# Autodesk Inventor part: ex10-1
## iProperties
Author: E. MOSS
Length Units: 11269
Angle Units: 11279
Time Units: 11290
Mass Units: 11283
Shininess: 3
Angle Display Precision: 2
Document Length Units: 11269
Document Angle Units: 11283
Document Time Units: 11279
Document Mass Units: 11290
Document Length Units Precision: 3
Document Angle Units Precision: 2
Compacted: False
PropertySet Name: _Private Model Information
Created: 2001-08
Part Number: ex10-1
Material: Aluminum-6061
Document SubType Name: Sheet Metal
Designer: E. MOSS
Control State: 0
Master: False
Checked Out: False
PropertySet Name: Design Tracking Control
Density: 0.0
Volumn: 0.0
Area: 0.0
PropertySet Name: Model Information
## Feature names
1. Hole1
2. Plate1
3. Plate2
4. Bend1
5. Plate3
6. Bend2
7. Plate4
8. Bend3
9. Plate5
10. Bend4
11. Plate6
12. Bend5
13. Plate7
14. Bend6
15. FlatPatternExtrusion1
